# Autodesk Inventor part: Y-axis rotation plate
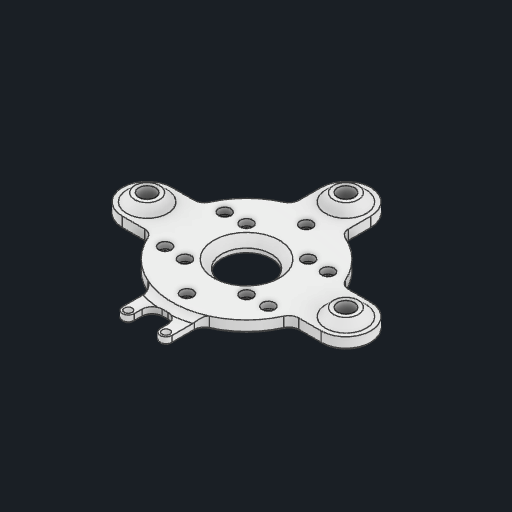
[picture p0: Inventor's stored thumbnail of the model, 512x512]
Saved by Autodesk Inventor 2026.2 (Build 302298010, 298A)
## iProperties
Created: 2026-04
Part Number: Y-axis rotation plate
Material: PBT 플라스틱
Document SubType Name: Modeling
Designer: work
Density: 1.31 g/cm^3
Appearance: 매끄러움 - 흰색
Author: work
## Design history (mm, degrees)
sketch "스케치1" dims "d28" = 6
  geometry: L1 (-15.5, 15.5)-(15.5, 15.5); L2 (15.5, 15.5)-(15.5, -15.5); L3 (15.5, -15.5)-(-15.5, -15.5); L4 (-15.5, -15.5)-(-15.5, 15.5); L5 (-15.5, 15.5)-(15.5, -15.5); L6 (15.5, 15.5)-(-15.5, -15.5); L7 (0, 0)-(50, 0); L8 (0, 0)-(0, -50); L9 (0, 0)-(-50, 0); L10 (35.355, 12.5)-(50, 12.5); L11 (35.355, -12.5)-(50, -12.5); L12 (12.5, 35.355)-(12.5, 50); L13 (-12.5, 35.355)-(-12.5, 50); L14 (-35.355, 12.5)-(-50, 12.5); L15 (-35.355, -12.5)-(-50, -12.5); L16 (-12.5, -35.355)-(-12.5, -50); L17 (12.5, -35.355)-(12.5, -50); L18 (-9.5, 50)-(9.5, 50); L19 (6.5, 50)-(6.5, 41); L20 (6.5, 41)-(-6.5, 41); L21 (-6.5, 41)-(-6.5, 50); L22 (12.5, 50)-(12.5, 35.355); L23 (-12.5, 50)-(-12.5, 35.355); C1 r 12.5 at (0, 0); C2 r 4.25 at (50, 0); C3 r 4.25 at (0, -50); C4 r 4.25 at (-50, 0); C5 r 2 at (15.5, 15.5); C6 r 2 at (-15.5, 15.5); C7 r 2 at (-15.5, -15.5); C8 r 2 at (15.5, -15.5); C9 r 2 at (0, -30); C10 r 2 at (25.981, -15); C11 r 2 at (25.981, 15); C12 r 2 at (0, 30); C13 r 2 at (-25.981, 15); C14 r 2 at (-25.981, -15); C15 r 2 at (9.5, 50); C16 r 2 at (-9.5, 50); A1 r 37.5 centre (0, 0) between (35.355, 12.5) and (35.355, -12.5); A2 r 12.5 centre (50, 0) between (50, -12.5) and (50, 12.5); A3 r 12.5 centre (0, 50) between (12.5, 50) and (-12.5, 50); A4 r 12.5 centre (-50, 0) between (-50, 12.5) and (-50, -12.5); A5 r 12.5 centre (0, -50) between (-12.5, -50) and (12.5, -50); A6 r 3 centre (9.5, 50) between (12.5, 50) and (6.5, 50); 13 further points
  constraints: 46 end point, 22 centre point, 13 coincident, 12 point on circle, 5 horizontal, 5 perpendicular, 4 equal length, 4 midpoint, 3 point on line, 3 tangent, 1 concentric, 1 vertical, 53 other
  dimensions: "d0" = 31 distance of L2.end L3.end; "d1" = 31 distance of L1.end L2.end; "d2" = 25 diameter of C1; "d3" = 50 distance of L7.start L7.end; "d4" = 50 distance of L7.start L8.end; "d5" = 8.5 diameter of C2; "d6" = 8.5 diameter of C3; "d7" = 50 distance of L7.start L9.end; "d8" = 8.5 diameter of C4; "d9" = 4 diameter of C5; "d10" = 4 diameter of C6; "d11" = 4 diameter of C7; "d12" = 4 diameter of C8; "d13" = 4 diameter of C9; "d14" = 30 distance of L7.start C9.centre; "d17" = 360 deg dimension on L7.start C9.centre (derived); "d19" = 75 diameter of A1; "d20" = 25 distance from line of point (42.678, 12.5) L11; "d23" = 360 deg dimension on L7.start A2.centre (derived); "d25" = 19 distance of L18.start L18.end; "d26" = 4 diameter of C15; "d27" = 4 diameter of C16; "d29" = 9 distance from line of L18.end L20
  node "스케치 - 원형 패턴1" dims "d17" = 360 deg (derived)
  node "스케치 - 원형 패턴2" dims "d23" = 360 deg (derived)
extrude "돌출1" new body sketch "스케치1" distance "d30" = 6; taper "d31" = 0 deg
extrude "돌출2" join sketch "스케치1" distance "d32" = 4; taper "d33" = 0 deg
extrude "돌출3" join sketch "스케치1" distance "d34" = 2; taper "d35" = 0 deg
sketch "스케치2"
  geometry: L1 (35.355, -12.5)-(50, -12.5) reference; L2 (50, 12.5)-(35.355, 12.5) reference; L3 (12.5, 35.355)-(12.5, 50) reference; L4 (-12.5, 50)-(-12.5, 35.355) reference; L5 (-35.355, 12.5)-(-50, 12.5) reference; L6 (-50, -12.5)-(-35.355, -12.5) reference; C1 r 4.25 at (-50, 0) reference; C2 r 4.25 at (50, 0) reference; C3 r 4.25 at (0, 50) reference; C4 r 2 at (25.981, 15) reference; C5 r 2 at (25.981, -15) reference; C6 r 2 at (0, -30) reference; C7 r 2 at (-25.981, -15) reference; C8 r 2 at (-25.981, 15) reference; C9 r 2 at (0, 30) reference; C10 r 2 at (-15.5, 15.5) reference; C11 r 2 at (15.5, 15.5) reference; C12 r 2 at (15.5, -15.5) reference; C13 r 2 at (-15.5, -15.5) reference; C14 r 12.5 at (0, 0) reference; C15 r 6.25 at (50, 0); A1 r 12.5 centre (50, 0) between (50, -12.5) and (50, 12.5) reference; A2 r 37.5 centre (0, 0) between (35.355, 12.5) and (12.5, 35.355) reference; A3 r 12.5 centre (0, 50) between (12.5, 50) and (-12.5, 50) reference; A4 r 37.5 centre (0, 0) between (-12.5, 35.355) and (-35.355, 12.5) reference; A5 r 12.5 centre (-50, 0) between (-50, 12.5) and (-50, -12.5) reference; A6 r 37.5 centre (0, 0) between (-35.355, -12.5) and (35.355, -12.5) reference; 1 further point
  constraints: 1 centre point, 1 coincident
  dimensions: "d36" = 2 radial gap between concentric circles of C15 C2
extrude "돌출4" join sketch "스케치2" distance "d37" = 4; taper "d38" = 0 deg
chamfer "모따기1" distance "d39" = 4; stored, may be unused: second distance "d40" = 2, angle "d41" = 45 deg
sketch "스케치4"
  geometry: L1 (35.355, -12.5)-(50, -12.5) reference; L2 (50, 12.5)-(35.355, 12.5) reference; L3 (12.5, 35.355)-(12.5, 50) reference; L4 (-12.5, 50)-(-12.5, 35.355) reference; L5 (-35.355, 12.5)-(-50, 12.5) reference; L6 (-50, -12.5)-(-35.355, -12.5) reference; C1 r 10.25 at (0, 50) reference; C2 r 2 at (-15.5, -15.5) reference; C3 r 2 at (15.5, -15.5) reference; C4 r 2 at (15.5, 15.5) reference; C5 r 2 at (-15.5, 15.5) reference; C6 r 2 at (0, 30) reference; C7 r 2 at (-25.981, 15) reference; C8 r 2 at (-25.981, -15) reference; C9 r 2 at (0, -30) reference; C10 r 2 at (25.981, -15) reference; C11 r 2 at (25.981, 15) reference; C12 r 10.25 at (50, 0) reference; C13 r 10.25 at (-50, 0) reference; A1 r 12.5 centre (50, 0) between (50, -12.5) and (50, 12.5) reference; A2 r 37.5 centre (0, 0) between (35.355, 12.5) and (12.5, 35.355) reference; A3 r 12.5 centre (0, 50) between (12.5, 50) and (-12.5, 50) reference; A4 r 37.5 centre (0, 0) between (-12.5, 35.355) and (-35.355, 12.5) reference; A5 r 12.5 centre (-50, 0) between (-50, 12.5) and (-50, -12.5) reference; A6 r 37.5 centre (0, 0) between (-35.355, -12.5) and (35.355, -12.5) reference; 11 further points
  constraints: 10 coincident
hole "구멍2" sketch "스케치4" at (0, 30), (15.5, 15.5), (25.981, 15), (15.5, -15.5), (25.981, -15), (0, -30), (-15.5, -15.5), (-15.5, 15.5), (-25.981, 15), (-25.981, -15) diameter "d52" = 4; stored, may be unused: countersink angle "d56" = 90 deg, drill point angle "d58" = 118 deg; dims "d53" = 6, "d54" = 6.2, "d55" = 3.2, "d57" = 8
fillet "모깎기1" dims "d59" = 5
chamfer "모따기2" distance "d60" = 1; stored, may be unused: second distance "d61" = 2, angle "d62" = 45 deg
node "솔리드1"
pattern_circular "원형 패턴1" dims angle "d43" = 360 deg
node "투영된 루프1"
node "투영된 루프2"
feature "A9D066F2-1C7D-4E18-AEED-F7BC21143FA4" dims "d52" = 4, "d53" = 6, "d54" = 6.2, "d55" = 3.2, "d56" = 90 deg, "d57" = 8, "d58" = 118 deg
